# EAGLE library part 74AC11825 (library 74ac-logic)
8-bit bus interface LATCH
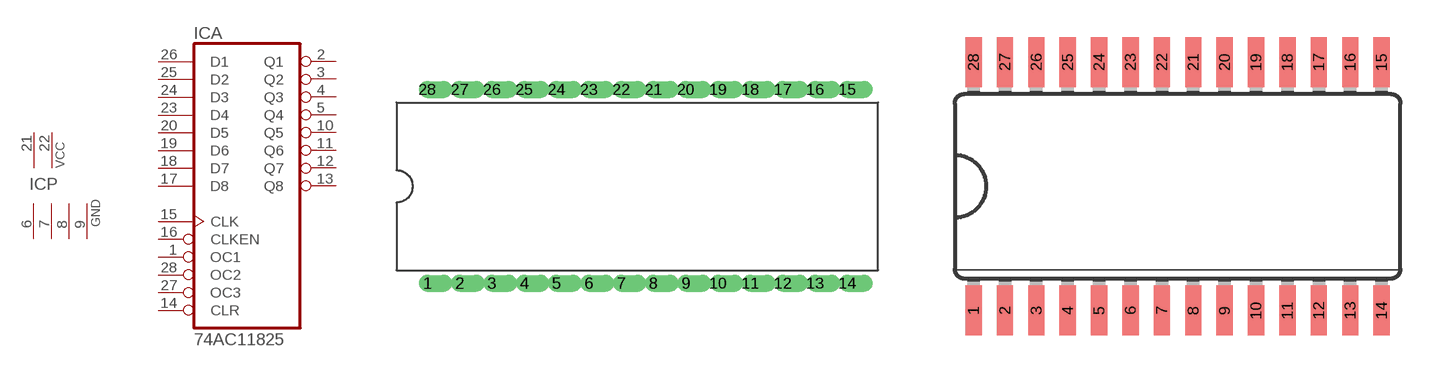
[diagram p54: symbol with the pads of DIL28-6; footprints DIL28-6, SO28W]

Designator prefix IC; gates A=7411825 P=2PWR4GND

## 74AC11825  [DIL28-6]
1  A:OC1  in
2  A:Q1  hiz
3  A:Q2  hiz
4  A:Q3  hiz
5  A:Q4  hiz
6  P:GND  pwr
7  P:GND  pwr
8  P:GND  pwr
9  P:GND  pwr
10  A:Q5  hiz
11  A:Q6  hiz
12  A:Q7  hiz
13  A:Q8  hiz
14  A:CLR  in
15  A:CLK  in
16  A:CLKEN  in
17  A:D8  in
18  A:D7  in
19  A:D6  in
20  A:D5  in
21  P:VCC  pwr
22  P:VCC  pwr
23  A:D4  in
24  A:D3  in
25  A:D2  in
26  A:D1  in
27  A:OC3  in
28  A:OC2  in

## 74AC11825D  [SO28W]
Pads as for DIL28-6

## Footprint DIL28-6 (pad centres in mm)
Dual In Line 0.6 inch
drill 0.813 offset: 1 -16.51,-7.62; 2 -13.97,-7.62; 3 -11.43,-7.62; 4 -8.89,-7.62; 5 -6.35,-7.62; 6 -3.81,-7.62; 7 -1.27,-7.62; 8 1.27,-7.62; 9 3.81,-7.62; 10 6.35,-7.62; 11 8.89,-7.62; 12 11.43,-7.62; 13 13.97,-7.62; 14 16.51,-7.62; 15 16.51,7.62; 16 13.97,7.62; 17 11.43,7.62; 18 8.89,7.62; 19 6.35,7.62; 20 3.81,7.62; 21 1.27,7.62; 22 -1.27,7.62; 23 -3.81,7.62; 24 -6.35,7.62; 25 -8.89,7.62; 26 -11.43,7.62; 27 -13.97,7.62; 28 -16.51,7.62

## Footprint SO28W (pad centres in mm)
Wide Small Outline package 300 mil
smd 0.66 x 2.032: 1 -8.255,-5.029; 2 -6.985,-5.029; 3 -5.715,-5.029; 4 -4.445,-5.029; 5 -3.175,-5.029; 6 -1.905,-5.029; 7 -0.635,-5.029; 8 0.635,-5.029; 9 1.905,-5.029; 10 3.175,-5.029; 11 4.445,-5.029; 12 5.715,-5.029; 13 6.985,-5.029; 14 8.255,-5.029; 15 8.255,5.029; 16 6.985,5.029; 17 5.715,5.029; 18 4.445,5.029; 19 3.175,5.029; 20 1.905,5.029; 21 0.635,5.029; 22 -0.635,5.029; 23 -1.905,5.029; 24 -3.175,5.029; 25 -4.445,5.029; 26 -5.715,5.029; 27 -6.985,5.029; 28 -8.255,5.029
